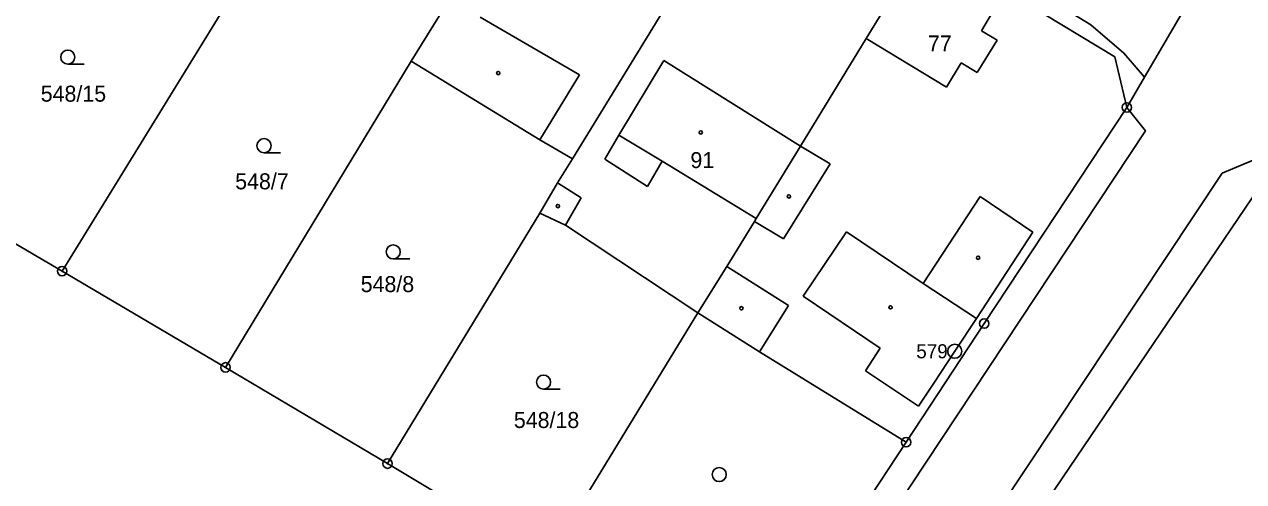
# Model space of a CAD drawing. Extents: x -758582 to -751794, y -998770 to -994350.
# Drawn here: x -754377.8 to -754248.1, y -997065.3 to -997016.7 of the extents above; entities that cross this region are included whole.
import ezdxf

# ---------------------------------------------------------------- set-up
doc = ezdxf.new("R2010")
doc.units = 0
for name, color, linetype in [('Hranice parcel', 7, 'Continuous'), ('Parcelní čísla', 7, 'Continuous'), ('Vnitřní kresba', 7, 'Continuous'), ('Značky bodu BP', 7, 'Continuous'), ('Značky budov', 7, 'Continuous'), ('Značky kultur', 7, 'Continuous')]:
    doc.layers.add(name, color=color, linetype=linetype)

msp = doc.modelspace()

# ---------------------------------------------------------------- linework, layer by layer
at = {"layer": 'Hranice parcel'}
for p, q in [((-754258.68, -997022.29), (-754252.12, -997011.03)), ((-754332.57, -997013.92), (-754336.66, -997020.59)), ((-754356.72, -997015.17), (-754373.8, -997042.91)), ((-754356.41, -997053.14), (-754336.66, -997020.59)), ((-754260.55, -997025.5), (-754258.68, -997022.29)), ((-754373.8, -997042.91), (-754383.59, -997037.19)), ((-754339.18, -997063.38), (-754322.99, -997036.73)), ((-754356.41, -997053.14), (-754373.8, -997042.91)), ((-754322.2, -997073.53), (-754306.17, -997047.33)), ((-754339.18, -997063.38), (-754356.41, -997053.14)), ((-754300.65, -997086.35), (-754284.03, -997061.1)), ((-754322.2, -997073.53), (-754339.18, -997063.38))]:
    msp.add_line(p, q, dxfattribs=at)
for points in [[(-754319.52, -997030.98), (-754300.11, -996999.31), (-754299.06, -996997.55)], [(-754281.08, -997006.49), (-754264.39, -997016.71), (-754260.86, -997019.73), (-754258.68, -997022.29)], [(-754281.98, -997007.92), (-754283.01, -997009.56), (-754288.27, -997018.16), (-754295.28, -997029.61), (-754299.99, -997037.3), (-754300.15, -997037.64), (-754303.11, -997042.42), (-754306.17, -997047.33)], [(-754260.55, -997025.5), (-754261.83, -997020.13), (-754281.98, -997007.92)], [(-754336.66, -997020.59), (-754322.98, -997028.93), (-754319.52, -997030.98)], [(-754284.03, -997061.1), (-754275.72, -997048.49), (-754260.55, -997025.5)], [(-754298.61, -997110.48), (-754287.65, -997094.76), (-754247.23, -997035.13), (-754244.34, -997029.93)], [(-754319.52, -997030.98), (-754321.11, -997033.52), (-754322.99, -997036.73)], [(-754322.99, -997036.73), (-754320.27, -997038.03), (-754306.17, -997047.33)], [(-754306.17, -997047.33), (-754299.61, -997051.5), (-754284.03, -997061.1)]]:
    msp.add_lwpolyline(points, dxfattribs=at)
at = {"layer": 'Vnitřní kresba'}
for p, q in [((-754276.01, -997017.34), (-754274.48, -997014.78)), ((-754329.32, -997015.89), (-754318.78, -997022.05)), ((-754274.36, -997018.36), (-754276.01, -997017.34)), ((-754288.27, -997018.16), (-754279.75, -997023.35)), ((-754276.47, -997021.78), (-754274.36, -997018.36)), ((-754309.79, -997020.51), (-754314.58, -997028.44)), ((-754309.79, -997020.51), (-754295.28, -997029.61)), ((-754279.75, -997023.35), (-754278.16, -997020.75)), ((-754278.16, -997020.75), (-754276.47, -997021.78)), ((-754322.98, -997028.93), (-754318.78, -997022.05)), ((-754260.55, -997025.5), (-754258.56, -997028)), ((-754298.18, -997087.75), (-754258.56, -997028)), ((-754314.58, -997028.44), (-754316.09, -997031)), ((-754309.99, -997031.22), (-754314.58, -997028.44)), ((-754295.28, -997029.61), (-754292.12, -997031.5)), ((-754250.41, -997032.48), (-754244.34, -997029.93)), ((-754311.54, -997033.91), (-754316.09, -997031)), ((-754311.54, -997033.91), (-754309.99, -997031.22)), ((-754299.99, -997037.3), (-754309.99, -997031.22)), ((-754297.07, -997039.47), (-754292.12, -997031.5)), ((-754318.58, -997035.12), (-754321.11, -997033.52)), ((-754290.57, -997092.9), (-754250.41, -997032.48)), ((-754318.58, -997035.12), (-754320.27, -997038.03)), ((-754282.23, -997044.21), (-754276.17, -997034.98)), ((-754276.17, -997034.98), (-754270.54, -997038.77)), ((-754300.15, -997037.64), (-754297.07, -997039.47)), ((-754290.37, -997038.74), (-754294.98, -997045.57)), ((-754290.37, -997038.74), (-754282.23, -997044.21)), ((-754270.54, -997038.77), (-754276.56, -997047.95)), ((-754303.11, -997042.42), (-754296.54, -997046.56)), ((-754282.23, -997044.21), (-754276.56, -997047.95)), ((-754294.98, -997045.57), (-754286.79, -997051.09)), ((-754296.54, -997046.56), (-754299.61, -997051.5)), ((-754278.85, -997051.43), (-754276.56, -997047.95)), ((-754288.36, -997053.52), (-754286.79, -997051.09)), ((-754281.09, -997054.82), (-754278.85, -997051.43)), ((-754288.36, -997053.52), (-754282.71, -997057.28)), ((-754282.71, -997057.28), (-754281.09, -997054.82))]:
    msp.add_line(p, q, dxfattribs=at)
at = {"layer": 'Značky bodu BP'}
for centre, radius in [((-754260.55, -997025.5), 0.5), ((-754260.55, -997025.5), 0.0303), ((-754373.8, -997042.91), 0.5), ((-754373.8, -997042.91), 0.0303), ((-754275.72, -997048.49), 0.5), ((-754275.72, -997048.49), 0.0303), ((-754278.85, -997051.43), 0.75), ((-754278.85, -997051.43), 0.03), ((-754356.41, -997053.14), 0.5), ((-754356.41, -997053.14), 0.0303), ((-754284.03, -997061.1), 0.5), ((-754284.03, -997061.1), 0.0303), ((-754339.18, -997063.38), 0.5), ((-754339.18, -997063.38), 0.0303)]:
    msp.add_circle(centre, radius, dxfattribs=at)
at = {"layer": 'Značky budov'}
for centre in [(-754327.41, -997021.85), (-754305.87, -997028.16), (-754296.5, -997034.97), (-754321.06, -997036), (-754276.37, -997041.48), (-754301.55, -997046.85), (-754285.68, -997046.76)]:
    msp.add_circle(centre, 0.175, dxfattribs=at)
at = {"layer": 'Značky kultur'}
for p, q in [((-754373.19, -997020.9), (-754371.44, -997020.9)), ((-754352.32, -997030.32), (-754350.57, -997030.32)), ((-754338.58, -997041.61), (-754336.83, -997041.61)), ((-754322.59, -997055.46), (-754320.84, -997055.46))]:
    msp.add_line(p, q, dxfattribs=at)
for centre in [(-754373.19, -997020.15), (-754352.32, -997029.57), (-754338.58, -997040.86), (-754322.59, -997054.71), (-754303.91, -997064.54)]:
    msp.add_circle(centre, 0.75, dxfattribs=at)

# ---------------------------------------------------------------- texts
at = {"layer": 'Parcelní čísla'}
for s, p in [('77', (-754281.71, -997019.55)), ('548/15', (-754376.07, -997024.89)), ('91', (-754306.97, -997031.95)), ('548/7', (-754355.39, -997034.21)), ('548/8', (-754342.04, -997045.14)), ('548/18', (-754325.75, -997059.59))]:
    msp.add_text(s, height=1.7, dxfattribs=at).set_placement(p)
at = {"layer": 'Značky bodu BP'}
msp.add_text('579', height=1.5, dxfattribs=at).set_placement((-754282.95, -997052.18))

doc.saveas('drawing.dxf')
